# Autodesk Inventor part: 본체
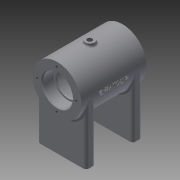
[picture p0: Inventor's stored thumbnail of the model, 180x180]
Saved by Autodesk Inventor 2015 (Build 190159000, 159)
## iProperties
Created: 2020-07
Part Number: 본체
Material: 일반
Document SubType Name: Modeling
Designer: 1015698
Density: 1 g/cm^3
Appearance: 기본값
Author: 1015698
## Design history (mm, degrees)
sketch "스케치1"
  geometry: L1 (-35, 0)-(35, 0); L2 (-35, 0)-(35, 0); L3 (35, 0)-(35, 26); L4 (35, 26)-(-35, 26); L5 (-35, 26)-(-35, 0); L6 (-35, 0)-(-23, 0); L7 (-23, 0)-(-23, 16); L8 (-23, 16)-(-35, 16); L9 (-35, 16)-(-35, 0); L10 (-23, 0)-(-21, 0); L11 (-21, 0)-(-21, 14); L12 (-21, 14)-(-23, 14); L13 (-23, 14)-(-23, 0); L14 (-21, 0)-(21, 0); L15 (21, 0)-(21, 21); L16 (21, 21)-(-21, 21); L17 (-21, 21)-(-21, 0); L18 (21, 0)-(23, 0); L19 (23, 0)-(23, 14); L20 (23, 14)-(21, 14); L21 (21, 14)-(21, 0); L22 (23, 0)-(35, 0); L23 (35, 0)-(35, 16); L24 (35, 16)-(23, 16); L25 (23, 16)-(23, 0); 2 further points
  constraints: 50 end point, 12 parallel, 7 horizontal, 6 perpendicular, 1 coincident, 1 midpoint, 1 point on line
  dimensions: "d0" = 70 distance of L1.start L1.end; "d1" = 52 diameter of L4 L1; "d2" = 12 distance of L7.end L8.end; "d3" = 12 distance of L23.end L24.end; "d4" = 2 distance of L11.end L12.end; "d5" = 42 distance of L15.end L16.end; "d6" = 2 distance of L19.end L20.end; "d7" = 28 diameter of L12 L1; "d8" = 28 diameter of L20 L1; "d9" = 32 diameter of L24 L1; "d10" = 32 diameter of L8 L1; "d11" = 42 diameter of L16 L1
revolve "회전1" sketch "스케치1" stored, may be unused: angle "d12" = 90 deg
fillet "모깎기1" dims "d13" = 0.3, "d14" = 3
sketch "스케치2" dims "d15" = 42
  geometry: C1 r 16 at (0, 0) reference; C2 r 26 at (0, 0) reference; 2 further points
  constraints: 2 vertical alignment, 1 coincident, 2 other
hole "구멍1" sketch "스케치2" at (0, 21) diameter "d16" = 3.242; stored, may be unused: countersink angle "d20" = 90 deg, drill point angle "d22" = 118 deg; dims "d17" = 8, "d18" = 4, "d19" = 2, "d21" = 10
node "작업 평면1"
sketch "스케치3"
  geometry: L1 (-64, -26)-(-64, 26); L2 (-64, 26)-(0, 26); L3 (0, -26)-(-64, -26); A1 r 26 centre (0, 0) between (0, 26) and (0, -26) reference; 1 further point
  constraints: 6 end point, 2 point on circle, 1 horizontal, 1 tangent
  dimensions: "d28" = 52 distance of L1.start L1.end; "d29" = 52 distance between parallel lines of L2 L3; "d30" = 64 distance from line of point (0, 0) L1
extrude "돌출1" join sketch "스케치3" distance "d31" = 10; taper "d32" = 0 deg
sketch "스케치4"
  geometry: L1 (0, 52)-(0, 0) reference; L2 (-10, 52)-(-10, 0) reference; L3 (-10, 26)-(-10, 46); L4 (-10, 46)-(0, 46); L5 (0, 0)-(0, 52) reference; L6 (-10, 26)-(-10, 6); L7 (-10, 6)-(0, 6); L8 (-5, 48.621)-(-5, 45.379) reference; 3 further points
  constraints: 8 end point, 5 point on line, 3 midpoint, 2 perpendicular
  dimensions: "d33" = 20 distance of L3.start L3.end; "d34" = 20 distance of L3.start L6.end
hole "구멍2" sketch "스케치4" at (-5, 6), (-5, 46) diameter "d35" = 4.134; stored, may be unused: countersink angle "d39" = 90 deg, drill point angle "d41" = 118 deg; dims "d36" = 10, "d37" = 4, "d38" = 2, "d40" = 10
node "작업 평면2"
sketch "스케치5"
  geometry: C1 r 5 at (0, 0); 1 further point
  constraints: 1 centre point, 1 coincident
  dimensions: "d43" = 10 diameter of C1
extrude "돌출2" join sketch "스케치5" stored distance "d44" = 10; taper "d45" = 0 deg
hole "구멍3" diameter "d48" = 5.188; stored, may be unused: countersink angle "d52" = 90 deg, drill point angle "d54" = 118 deg; dims "d46" = 10, "d47" = 10, "d49" = 12, "d50" = 4, "d51" = 2, "d53" = 16
sketch "스케치6"
  geometry: L1 (0, 0)-(-43.955, 0); L2 (0, 0)-(-27.251, -9.919)
  constraints: 4 end point, 1 horizontal
  dimensions: "d55" = 29 distance of L1.start L2.end; "d56" = 20 deg angle of L2 L1
node "작업 평면3"
sketch "스케치7"
  geometry: C1 r 6 at (0, 0); 1 further point
  constraints: 1 centre point, 1 coincident
  dimensions: "d57" = 12 diameter of C1
extrude "돌출3" join sketch "스케치7" stored distance "d58" = 10; taper "d59" = 0 deg
hole "구멍4" diameter "d62" = 5.188; stored, may be unused: countersink angle "d66" = 90 deg, drill point angle "d68" = 118 deg; dims "d60" = 10, "d61" = 10, "d63" = 12, "d64" = 4, "d65" = 2, "d67" = 16
node "작업 평면4"
sketch "스케치8"
  geometry: L1 (-35, -26)-(-35, 26) reference; L2 (-35, 26)-(35, 26) reference; 2 further points
  constraints: 1 other
  dimensions: "d70" = 35 distance from line of L1 point (0, 0); "d71" = 26 distance from line of L2 point (0, 0)
feature "엠보싱1" sketch "스케치8" dims "d10" = 32, "d72" = 0.5, "d73" = 0
chamfer "모따기1" distance "d74" = 1; stored, may be unused: second distance "d75" = 2, angle "d76" = 45 deg
fillet "모깎기2" dims "d77" = 2, "d78" = 3
node "솔리드1"
pattern_circular "원형 패턴1" dims angle "d24" = 360 deg
mirror "대칭1"
mirror "대칭2"
other parameters: "d42" = 29
